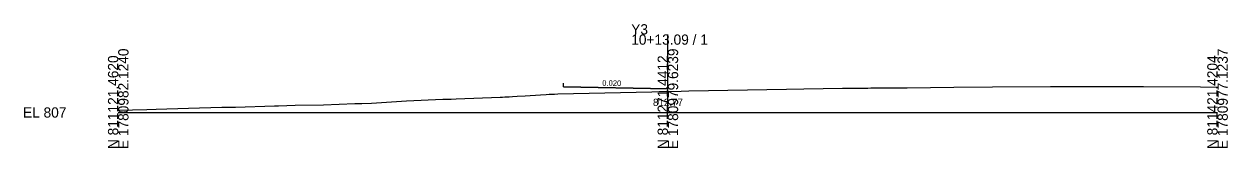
# Model space of a CAD drawing. Extents: x -26 to 303, y -10 to 4017.
# Drawn here: x -25.7 to 302.8, y 490.3 to 524.2 of the extents above; entities that cross this region are included whole.
import ezdxf

# ---------------------------------------------------------------- set-up
doc = ezdxf.new("R2010")
doc.units = 0
for name, color, linetype in [('Exist Cross Section Cell', 7, 'Continuous'), ('Exist XS Center Line Elevation Label', 7, 'Continuous'), ('Exist XS Ground Line', 7, 'Continuous'), ('Prop XS Dump Level', 7, 'Continuous'), ('Prop XS EOT Tick Mark', 7, 'Continuous'), ('Prop XS Finish Grade Pavement', 7, 'Continuous'), ('Prop XS SE Text', 7, 'Continuous'), ('Prop XS Subgrade Earthwork', 7, 'Continuous')]:
    doc.layers.add(name, color=color, linetype=linetype)

msp = doc.modelspace()

# ---------------------------------------------------------------- linework, layer by layer
at = {"layer": 'Exist Cross Section Cell'}
for p, q in [((150, 500), (150, 521.32)), ((0, 500), (150, 500)), ((150, 500), (300, 500))]:
    msp.add_line(p, q, dxfattribs=at)
at = {"layer": 'Exist XS Ground Line'}
for p, q in [((155.68, 505.89), (182.37, 506.37)), ((182.37, 506.37), (187.14, 506.46)), ((187.14, 506.46), (197.7, 506.61)), ((197.7, 506.61), (202.57, 506.64)), ((202.57, 506.64), (203.15, 506.66)), ((203.15, 506.66), (203.76, 506.68)), ((203.76, 506.68), (204.56, 506.68)), ((204.56, 506.68), (205.38, 506.69)), ((205.38, 506.69), (206.26, 506.7)), ((206.26, 506.7), (207.16, 506.72)), ((207.16, 506.72), (215.29, 506.78)), ((215.29, 506.78), (228.06, 506.92)), ((228.06, 506.92), (238.59, 507.01)), ((238.59, 507.01), (254.43, 507.08)), ((254.43, 507.08), (258, 507.08)), ((258, 507.08), (277.08, 507.11)), ((277.08, 507.11), (279.76, 507.1)), ((279.76, 507.1), (295.4, 506.99)), ((295.4, 506.99), (300, 506.95)), ((69.14, 502.55), (78.66, 503.2)), ((78.66, 503.2), (88.6, 503.6)), ((88.6, 503.6), (90.85, 503.67)), ((90.85, 503.67), (92.23, 503.72)), ((92.23, 503.72), (104.21, 504.21)), ((104.21, 504.21), (104.84, 504.23)), ((104.84, 504.23), (105.53, 504.26)), ((105.53, 504.26), (106.07, 504.28)), ((106.07, 504.28), (106.69, 504.32)), ((106.69, 504.32), (107.63, 504.37)), ((107.63, 504.37), (108.84, 504.44)), ((108.84, 504.44), (111.09, 504.58)), ((111.09, 504.58), (115.2, 504.83)), ((115.2, 504.83), (116.81, 504.93)), ((116.81, 504.93), (117.63, 504.98)), ((117.63, 504.98), (119.1, 505.03)), ((119.1, 505.03), (119.98, 505.06)), ((119.98, 505.06), (145.65, 505.68)), ((145.65, 505.68), (147.63, 505.72)), ((147.63, 505.72), (148.01, 505.73)), ((148.01, 505.73), (150, 505.77)), ((150, 505.77), (153.59, 505.85)), ((153.59, 505.85), (155.68, 505.89)), ((0, 500.62), (7.79, 500.85)), ((7.79, 500.85), (10.33, 500.91)), ((10.33, 500.91), (19.14, 501.18)), ((19.14, 501.18), (28.23, 501.45)), ((28.23, 501.45), (32.05, 501.49)), ((32.05, 501.49), (42.66, 501.81)), ((42.66, 501.81), (43.76, 501.85)), ((43.76, 501.85), (48.28, 502)), ((48.28, 502), (56.06, 502.1)), ((56.06, 502.1), (64.6, 502.41)), ((64.6, 502.41), (66.46, 502.44)), ((66.46, 502.44), (69.14, 502.55))]:
    msp.add_line(p, q, dxfattribs=at)
at = {"layer": 'Prop XS Dump Level'}
msp.add_line((150, 506.48), (121.49, 507.04), dxfattribs=at)
at = {"layer": 'Prop XS EOT Tick Mark'}
msp.add_line((121.49, 507.04), (121.49, 508.04), dxfattribs=at)
at = {"layer": 'Prop XS Finish Grade Pavement'}
msp.add_line((121.49, 507.04), (150, 506.48), dxfattribs=at)
at = {"layer": 'Prop XS Subgrade Earthwork'}
msp.add_line((150, 505.86), (150, 505.77), dxfattribs=at)

# ---------------------------------------------------------------- texts
at = {"layer": 'Exist Cross Section Cell'}
for s, p in [('Y3', (140, 521.32)), ('10+13.09 / 1', (140, 518.52)), ('EL 807', (-26, 498.6))]:
    msp.add_text(s, height=2.8, dxfattribs=at).set_placement(p)
for s, p in [('E 1780982.1240', (2.8, 490)), ('E 1780979.6239', (152.8, 490)), ('E 1780977.1237', (302.8, 490)), ('N 811121.4620', (0, 490)), ('N 811271.4412', (150, 490)), ('N 811421.4204', (300, 490))]:
    msp.add_text(s, height=2.8, rotation=90, dxfattribs=at).set_placement(p)
at = {"layer": 'Exist XS Center Line Elevation Label'}
msp.add_text('812.77', height=2, dxfattribs=at).set_placement((145.94, 501.77))
at = {"layer": 'Prop XS SE Text'}
msp.add_text('0.020', height=1.5, rotation=358.8771, dxfattribs=at).set_placement((132.08, 507.33))

doc.saveas('drawing.dxf')
